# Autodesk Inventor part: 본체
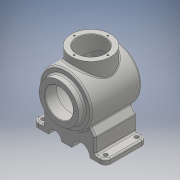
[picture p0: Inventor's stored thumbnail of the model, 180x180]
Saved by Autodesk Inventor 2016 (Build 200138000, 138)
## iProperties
Created: 2018-08
Part Number: 본체
Material: 일반
Document SubType Name: Modeling
Designer: USER
Density: 1 g/cm^3
Appearance: 기본값
Author: USER
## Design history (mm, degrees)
sketch "스케치1"
  geometry: C1 r 38 at (0, 0); 1 further point
  constraints: 1 centre point, 1 coincident
  dimensions: "d0" = 76 diameter of C1
extrude "돌출1" new body sketch "스케치1" distance "d1" = 12; taper "d2" = 0 deg
sketch "스케치2"
  geometry: L1 (0, 38)-(0, -38) reference; L2 (0, 0)-(-43.367, 0); L3 (12, 50)-(108.671, 50); L4 (120, 0)-(120, 54.462); L5 (120, 0)-(12, 0); L6 (12, 0)-(12, 39); L7 (12, 50)-(12, 0); A1 r 116 centre (4, 0) between (120, 0) and (108.671, 50); 4 further points; 1 other entity
  constraints: 12 end point, 7 horizontal alignment, 2 horizontal, 2 midpoint, 2 point on circle, 2 vertical alignment, 1 centre point, 1 perpendicular, 1 vertical, 1 other
  dimensions: "d6" = 100 diameter of L3 L2; "d9" = 116 radius of A1; "d10" = 108 distance between parallel lines of L4 L7
revolve "회전1" sketch "스케치2" stored, may be unused: angle "d11" = 90 deg
node "작업 평면1"
sketch "스케치3"
  geometry: L1 (-70, 20)-(70, 20); L2 (70, 20)-(70, 100); L3 (70, 100)-(-70, 100); L4 (-70, 100)-(-70, 20); L5 (50, 12)-(-50, 12) reference; 2 further points
  constraints: 8 end point, 2 parallel, 1 horizontal, 1 midpoint, 1 perpendicular, 1 vertical alignment
  dimensions: "d13" = 140 distance of L1.start L1.end; "d14" = 80 distance of L3.end L1.start; "d15" = 8 distance between parallel lines of L1 L5
extrude "돌출2" join sketch "스케치3" distance "d16" = 10; taper "d17" = 0 deg
node "작업 평면2"
sketch "스케치4"
  geometry: L1 (140, 0)-(0, 0); L2 (0, 0)-(0, 10); L3 (70, 10)-(20, 10); L4 (140, 0)-(140, 10); L5 (140, 10)-(0, 10) reference; L6 (20, 10)-(20, 38.563); L7 (20, 38.563)-(29.696, 52.41); L8 (20, 10)-(70, 10); L9 (20, 38.563)-(0, 10); L10 (70, 10)-(70, 32); A1 r 50 centre (70, 82) between (29.696, 52.41) and (70, 32) reference; 1 further point
  constraints: 12 end point, 2 point on circle, 1 collinear, 1 perpendicular, 1 point on line, 1 vertical
  dimensions: "d24" = 20 horizontal distance of L2.end L6.end; "d25" = 35 deg angle of L2 L9; "d27" = 29.69578 horizontal distance of L2.end L7.end; "d28" = 22 distance of L3.start L10.end
feature "리브1" sketch "스케치4" dims "d29" = 1, "d30" = 80, "d31" = 0, "d32" = 0, "d33" = 1, "d34" = 1
node "작업 평면3"
sketch "스케치6"
  geometry: L1 (140, 0)-(140, 10) reference; L2 (140, 10)-(70, 10) reference; L3 (120, 10)-(120, 38.563); L4 (120, 38.563)-(110.304, 52.41); 2 further points
  constraints: 4 end point, 1 point on line, 1 vertical, 2 other
  dimensions: "d54" = 20 distance between parallel lines of L1 L3; "d56" = 35 deg angle of L1 L4; "d57" = 29.69578 horizontal distance of L1.end L4.end
feature "리브3" sketch "스케치6" dims "d58" = 1, "d59" = 80, "d60" = 0, "d61" = 0, "d62" = 1, "d63" = 1
sketch "스케치7"
  geometry: C1 r 27 at (0, 0); 1 further point
  constraints: 1 centre point, 1 coincident
  dimensions: "d64" = 54 diameter of C1
extrude "돌출3" cut sketch "스케치7" distance "d65" = 22; taper "d66" = 0 deg
sketch "스케치8"
  geometry: L1 (0, 0)-(-23.539, 0); L2 (22, 40)-(102.163, 40); L3 (22, 40)-(22, 0); L4 (22, -27)-(22, 27) reference; L5 (108.671, -50)-(108.671, 50) reference; L6 (22, 0)-(110, 0); A1 r 116 centre (4, 0) between (108.671, -50) and (108.671, 50) reference; A2 r 106 centre (4, 0) between (110, 0) and (102.163, 40)
  constraints: 8 end point, 2 horizontal, 2 point on circle, 1 centre point, 1 midpoint, 1 perpendicular
  dimensions: "d68" = 80 diameter of L2 L1; "d69" = 40 distance of L2.start L3.end; "d70" = 10 radial gap between concentric circles of A2 A1
revolve "회전2" sketch "스케치8" stored, may be unused: angle "d71" = 90 deg
node "작업 평면4"
sketch "스케치9"
  geometry: L1 (50, 12)-(-50, 12) reference; C1 r 38 at (0, 62); 2 further points
  constraints: 1 centre point, 1 midpoint, 1 vertical alignment
  dimensions: "d73" = 76 diameter of C1; "d74" = 50 distance from line of L1 C1.centre
extrude "돌출4" join sketch "스케치9" stored distance "d75" = 22; taper "d76" = 0 deg
sketch "스케치10"
  geometry: C1 r 38 at (0, 0) reference; C2 r 27 at (0, 0); 1 further point
  constraints: 1 centre point, 1 coincident
  dimensions: "d77" = 54 diameter of C2
extrude "돌출5" cut sketch "스케치10" distance "d78" = 50; taper "d79" = 0 deg
sketch "스케치11"
  geometry: C1 r 38 at (0, 0) reference; 2 further points
  constraints: 1 vertical alignment
  dimensions: "d80" = 32.5 distance of C1.centre point (0, 32.5)
hole "구멍1" sketch "스케치11" at (0, 32.5) diameter "d81" = 3.242; stored, may be unused: countersink angle "d85" = 90 deg, drill point angle "d87" = 118 deg; dims "d82" = 8, "d83" = 4, "d84" = 2, "d86" = 10
sketch "스케치12"
  geometry: 2 further points
  constraints: 1 vertical alignment
  dimensions: "d91" = 32.5 distance of point (0, 0) point (0, 32.5)
hole "구멍2" sketch "스케치12" at (0, 32.5) diameter "d92" = 3.242; stored, may be unused: countersink angle "d96" = 90 deg, drill point angle "d98" = 118 deg; dims "d93" = 8, "d94" = 4, "d95" = 2, "d97" = 10
sketch "스케치13"
  geometry: L1 (0, 0)-(140, 0) reference; L2 (140, 0)-(0, 0) reference; L3 (70, 0)-(70, 18.218); L4 (30, 0)-(55, 0); L5 (75, 0)-(110, 0); A1 r 12.5 centre (42.5, 0) between (55, 0) and (30, 0); A2 r 17.5 centre (92.5, 0) between (110, 0) and (75, 0); 2 further points
  constraints: 6 end point, 6 point on line, 4 point on circle, 2 centre point, 2 collinear, 2 midpoint, 1 horizontal alignment, 1 vertical
  dimensions: "d102" = 27.5 distance from line of A1.centre L3; "d103" = 12.5 radius of A1; "d104" = 22.5 distance from line of A2.centre L3; "d105" = 17.5 radius of A2
extrude "돌출6" cut sketch "스케치13" stored distance "d106" = 50; taper "d107" = 0 deg
extrude "돌출7" cut sketch "스케치13" stored distance "d108" = 50; taper "d109" = 0 deg
fillet "모깎기1" dims "d110" = 10
sketch "스케치14"
  geometry: L1 (-70, 90)-(-70, 30) reference; L2 (-40, 100)-(-60, 100) reference; L3 (-40, 100)-(-40, 20) reference; L4 (-60, 20)-(-40, 20) reference; C1 r 4 at (-60, 90); A1 r 10 centre (-60, 30) between (-70, 30) and (-60, 20) reference; A2 r 10 centre (-60, 90) between (-60, 100) and (-70, 90) reference; 1 further point
  constraints: 1 centre point, 1 coincident
  dimensions: "d111" = 8 diameter of C1
extrude "돌출8" cut sketch "스케치14" stored distance "d112" = 50; taper "d113" = 0 deg
fillet "모깎기2" dims "d114" = 3
fillet "모깎기3" dims "d115" = 3
fillet "모깎기4" dims "d116" = 3
fillet "모깎기5" dims "d117" = 3
fillet "모깎기6" dims "d118" = 3
chamfer "모따기1" distance "d119" = 1; stored, may be unused: second distance "d120" = 2, angle "d121" = 45 deg
chamfer "모따기2" distance "d122" = 1; stored, may be unused: second distance "d123" = 2, angle "d124" = 45 deg
node "작업 평면5"
sketch "스케치15"
  geometry: 2 further points
  constraints: 1 vertical alignment, 1 other
  dimensions: "d125" = 32.5 distance of point (0, 32.5) point (0, 0)
feature "엠보싱1" sketch "스케치15" dims "d126" = 0.5, "d127" = 0
fillet "모깎기7" dims "d128" = 3
fillet "모깎기10" dims "d131" = 3
fillet "모깎기11" dims "d132" = 3
fillet "모깎기12" dims "d133" = 3
fillet "모깎기15" dims "d136" = 3
fillet "모깎기16" dims "d137" = 3
fillet "모깎기17" dims "d138" = 3
fillet "모깎기18" dims "d139" = 3
node "솔리드1"
pattern_circular "원형 패턴1" dims angle "d89" = 360 deg
pattern_circular "원형 패턴2" dims angle "d100" = 360 deg
mirror "대칭1"
mirror "대칭2"
mirror "대칭4"
mirror "대칭5"
node "투영된 루프2"
node "투영된 루프3"
node "투영된 루프4"
other parameters: "d12" = -82, "d36" = 35 deg, "d55" = 35 deg, "d67" = 10, "d72" = -147
